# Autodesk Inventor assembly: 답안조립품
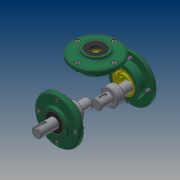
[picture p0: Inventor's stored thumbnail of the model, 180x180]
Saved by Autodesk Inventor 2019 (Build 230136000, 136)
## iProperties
Created: 2019-03
Part Number: 답안조립품
Material: 일반
Document SubType Name: Assembly
Designer: PC312-13
Author: PC312-13
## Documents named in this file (10)
- C:\Users\PC312-13\Desktop\490314V1001\답안조립품.iam
- C:\Users\PC312-13\Desktop\490314V1001\본체.ipt
- C:\Users\PC312-13\Desktop\490314V1001\커버.ipt
- C:\Users\PC312-13\Desktop\490314V1001\오일 실.ipt
- 오일 실.ipt
- C:\Users\PC312-13\Desktop\490314V1001\볼트 M4.ipt
- 볼트 M4.ipt
- C:\Users\PC312-13\Desktop\490314V1001\메인 축.ipt
- 메인 축.ipt
- C:\Users\PC312-13\Desktop\490314V1001\베어링 6203.ipt
